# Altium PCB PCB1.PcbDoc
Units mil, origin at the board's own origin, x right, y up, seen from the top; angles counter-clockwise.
Board outline 2484.29 x 2484.29 mil, 2 copper layers (Top Layer, Bottom Layer); 25 components, 9 nets, 53 pads, 3 vias.
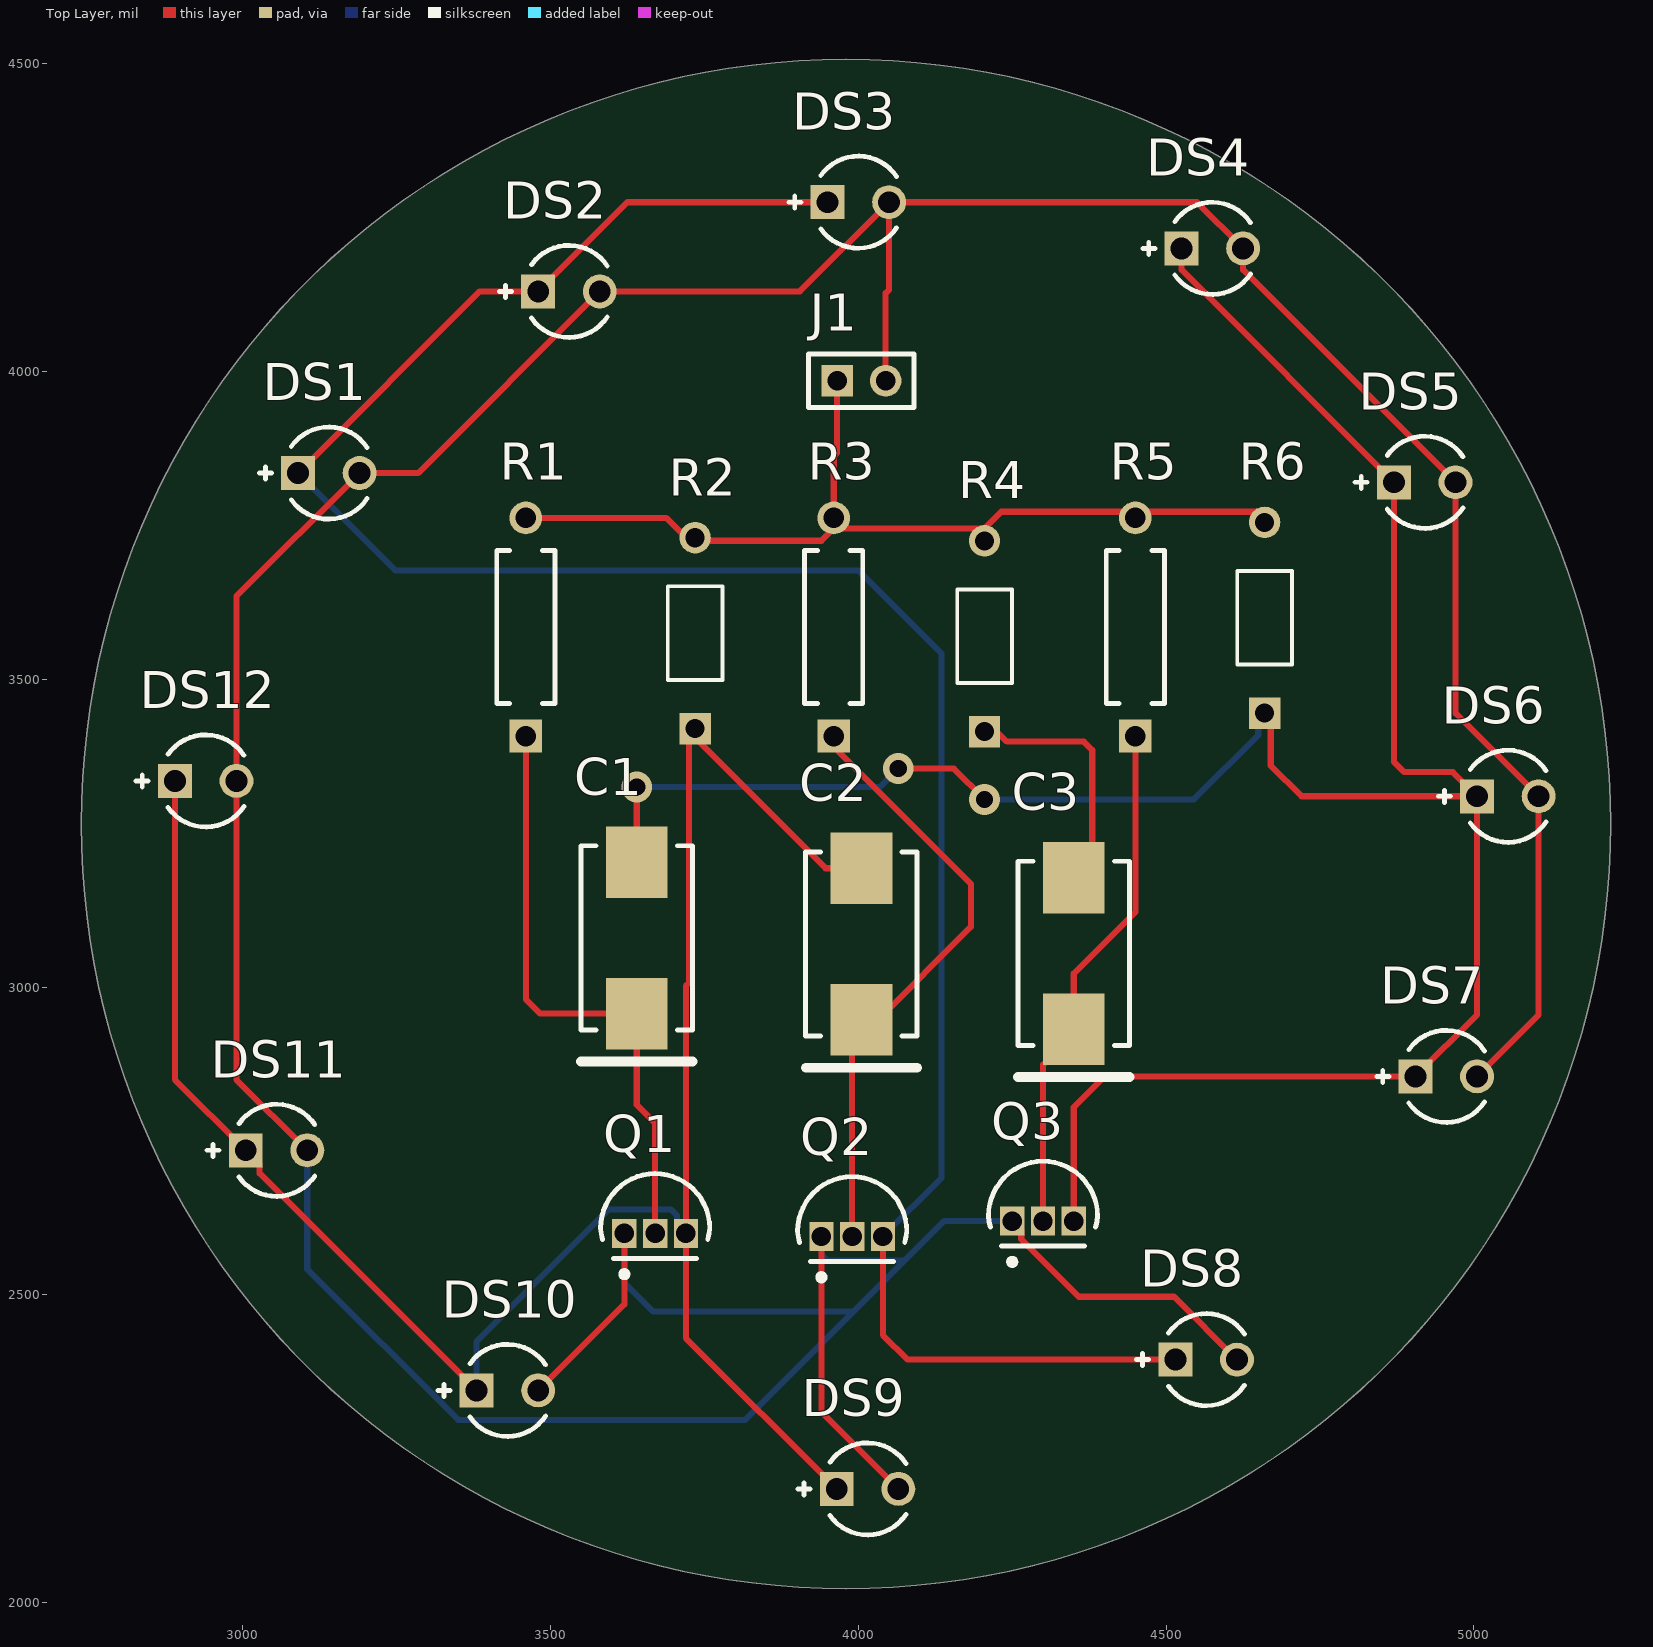
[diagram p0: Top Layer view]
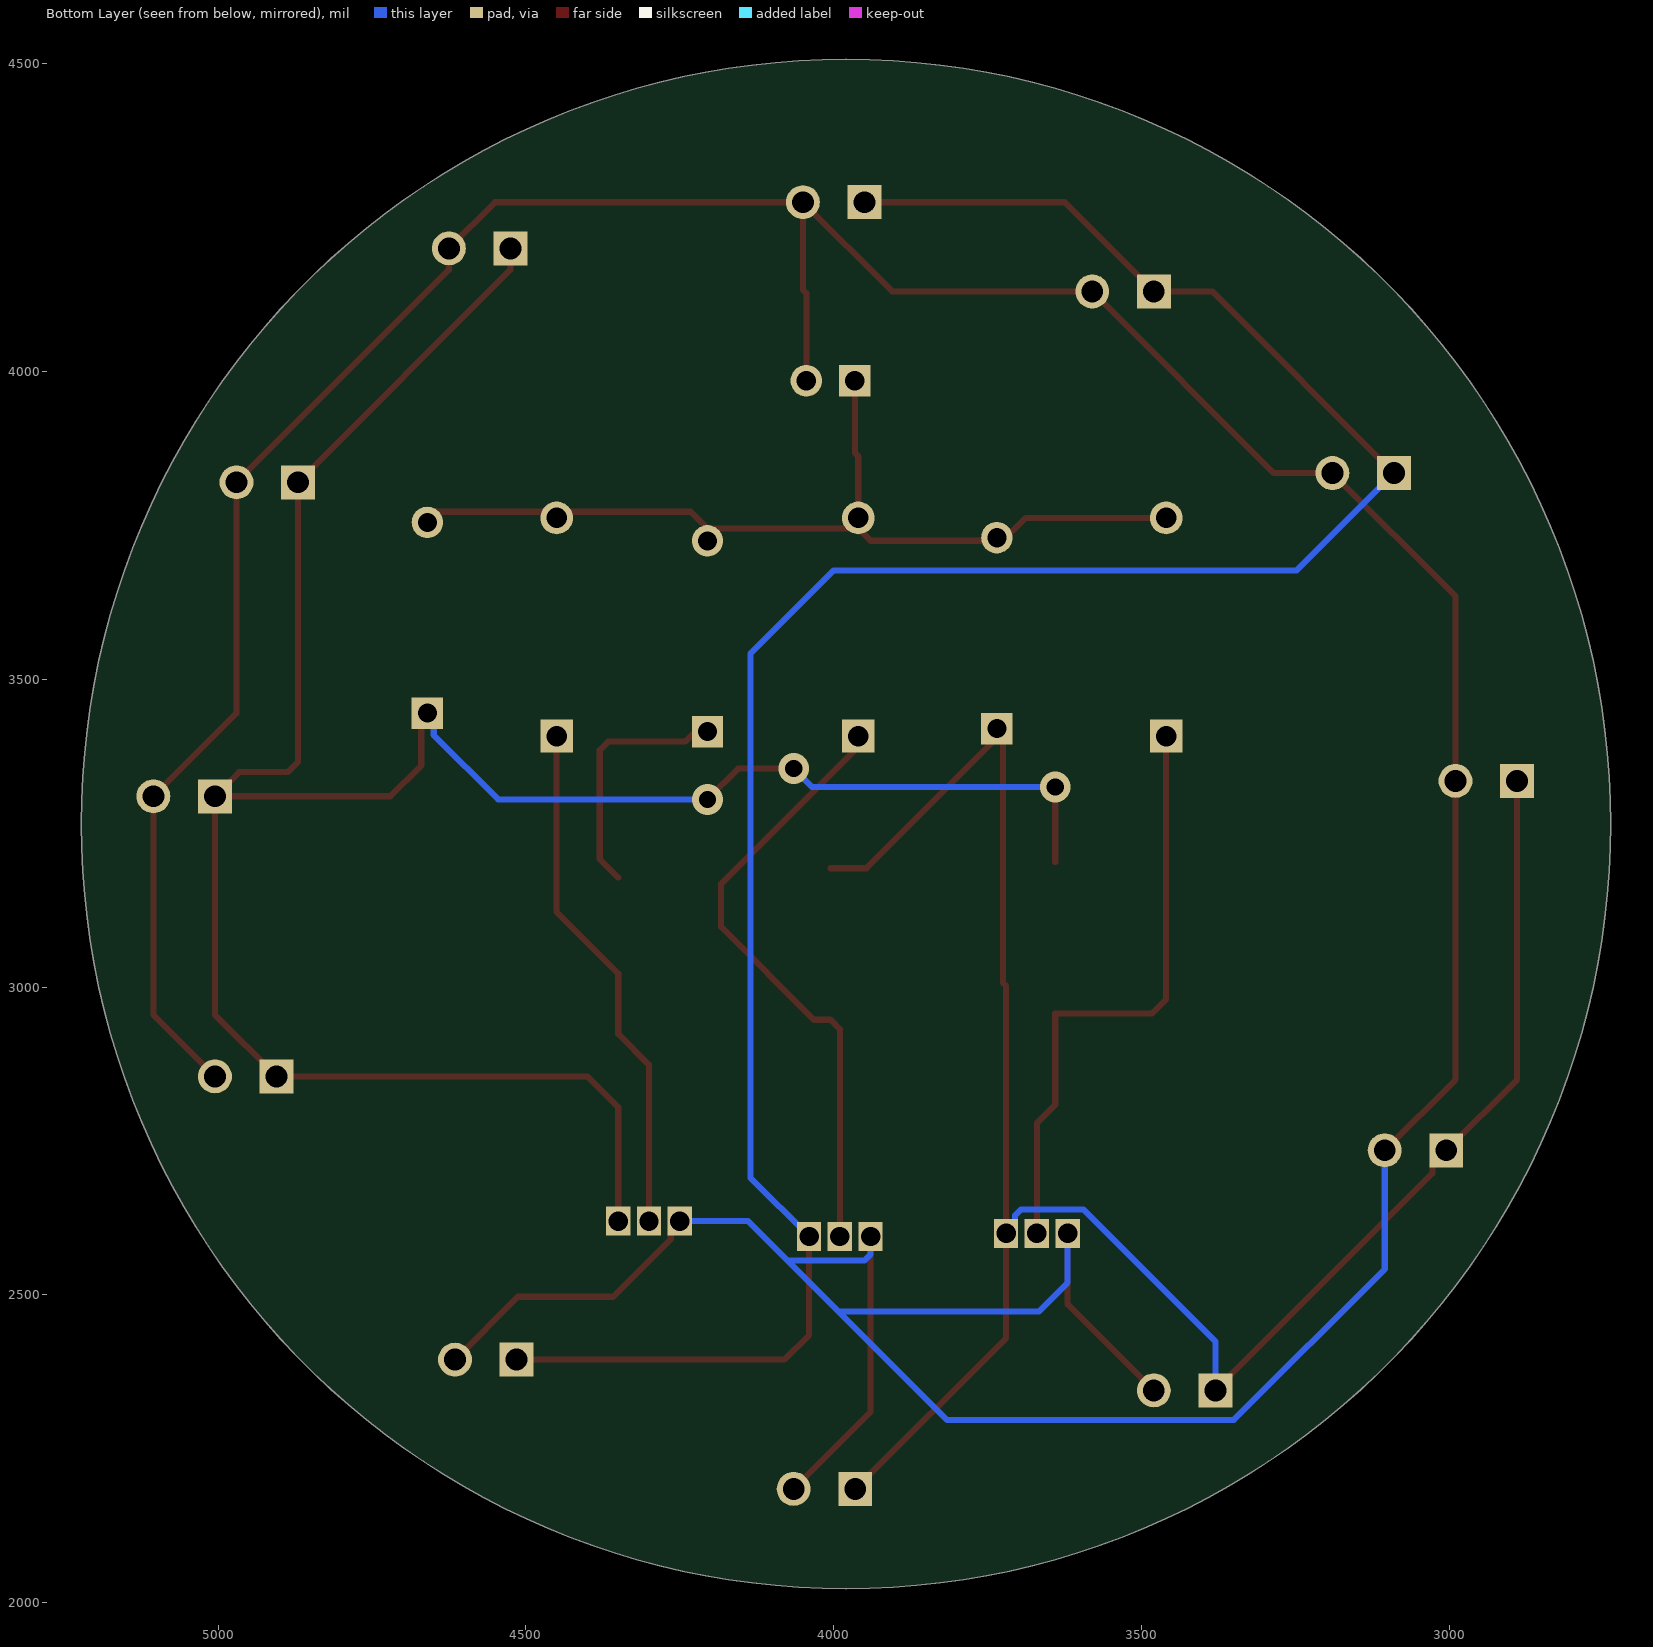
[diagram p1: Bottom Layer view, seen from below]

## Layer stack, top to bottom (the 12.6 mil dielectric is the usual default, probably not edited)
Top Solder: solder mask 0.4, Solder Resist, Dk 3.5
Top Layer: signal copper 1.4
Dielectric 1: dielectric 12.6, FR-4, Dk 4.8
Bottom Layer: signal copper 1.4
Bottom Solder: solder mask 0.4, Solder Resist, Dk 3.5

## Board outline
2737.85,3265 ccw(c3980,3265) 3980,2022.85 ccw(c3980,3265) 5222.15,3265 ccw(c3980,3265) 3980,4507.15 ccw(c3980,3265)

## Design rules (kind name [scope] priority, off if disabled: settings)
Clearance [All] p1: gap=10 ignorepadtopadclearanceinfootprint=FALSE
PolygonConnect [All] p1: connectstyle=Relief reliefconductorwidth=10 reliefentries=4 polygonreliefangle="90 Angle" airgapwidth=10
RoutingVias [All] p1: holewidth=28 width=50 viastyle="Through Hole" minholewidth=28 minwidth=50 maxholewidth=28 maxwidth=50
SolderMaskExpansion [All] p1: expansion=0 istentingtop=FALSE
SupplyNets "Schematic Supply Nets" [InNet('GND')] p1: voltage=0.000
Width [All] p1: maxlimit=10 minlimit=10 preferedwidth=10
30 further rules are at their usual default settings.

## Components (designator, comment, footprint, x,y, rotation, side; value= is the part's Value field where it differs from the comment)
C1 "T491D226K020AT" KEMT-T491-D_M 3640,3080 r90 top value=22µF
C2 "T491D226K020AT" KEMT-T491-D_M 4005,3070 r90 top value=22µF
C3 "T491D226K020AT" KEMT-T491-D_M 4350,3055 r90 top value=22µF
DS1 "LTL-1CHE" INDPR60-254-520X380X650 3140,3835 r0 top
DS2 "LTL-1CHE" INDPR60-254-520X380X650 3530,4130 r0 top
DS3 "LTL-1CHE" INDPR60-254-520X380X650 4000,4275 r0 top
DS4 "LTL-1CHE" INDPR60-254-520X380X650 4575,4200 r0 top
DS5 "LTL-1CHE" INDPR60-254-520X380X650 4920,3820 r0 top
DS6 "LTL-1CHE" INDPR60-254-520X380X650 5055,3310 r0 top
DS7 "LTL-1CHE" INDPR60-254-520X380X650 4955,2855 r0 top
DS8 "LTL-1CHE" INDPR60-254-520X380X650 4565,2395 r0 top
DS9 "LTL-1CHE" INDPR60-254-520X380X650 4015,2185 r0 top
DS10 "LTL-1CHE" INDPR60-254-520X380X650 3430,2345 r0 top
DS11 "LTL-1CHE" INDPR60-254-520X380X650 3055,2735 r0 top
DS12 "LTL-1CHE" INDPR60-254-520X380X650 2940,3335 r0 top
J1 "M22-2510205" FP-M22-2510205-MFG 4005,3985 r0 top
Q1 "S9013" JSCJ-TO-92-3_V 3670,2600 r0 top
Q2 "S9013" JSCJ-TO-92-3_V 3990,2595 r0 top
Q3 "S9013" JSCJ-TO-92-3_V 4300,2620 r0 top
R1 "MFR-25FBF52-10K" RESA60-630X240 3460,3585 r90 top value=10k
R2 "CF18JT330R" STA_CF18_STP 3735,3420 r90 top value=330
R3 "MFR-25FBF52-10K" RESA60-630X240 3960,3585 r90 top value=10k
R4 "CF18JT330R" STA_CF18_STP 4205,3415 r90 top value=330
R5 "MFR-25FBF52-10K" RESA60-630X240 4450,3585 r90 top value=10k
R6 "CF18JT330R" STA_CF18_STP 4660,3445 r90 top value=330

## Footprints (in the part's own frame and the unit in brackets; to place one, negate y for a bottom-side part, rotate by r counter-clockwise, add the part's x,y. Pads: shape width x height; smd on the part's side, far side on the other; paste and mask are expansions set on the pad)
FP-M22-2510205-MFG [mm]
  rect 1.3x1.3 hole 0.8 paste-2539.97 mask+0: 1(-1,0)
  round 1.3 hole 0.8 paste-2539.97 mask+0: 2(1,0)
  silkscreen extent -2.18,-1.1 2.18,1.1, body extent -2.27,-1.2 2.27,1.2, height 0.25
INDPR60-254-520X380X650 [mm] "THD, 2-Leads, Dia 3.8mm, Pitch 2.54mm"
  rect 1.4x1.4 hole 0.9: 1(-1.27,0)
  round 1.4 hole 0.9: 2(1.27,0)
  silkscreen extent -2.87,-1.9 1.58,1.9, body extent -1.9,-1.9 1.9,1.9, height 6.5
JSCJ-TO-92-3_V [mm] "TO-92, 3-leads, Height 4.7mm, Pitch 1.27mm"
  rect 1x1.2 hole 0.8: 1(-1.27,0) 2(0,0) 3(1.27,0)
  silkscreen extent -2.25,-1.81 2.25,2.47, body extent -2.25,-1.03 2.25,2.47, height 4.7
KEMT-T491-D_M [mm] "Molded Capacitor, 2-Leads, Body 7.60x4.60mm, IPC Low Density"
  rect 2.95x2.55 smd: 1(-3.125,0) 2(3.125,0)
  silkscreen extent -5.1,-2.3 3.8,2.3, body extent -3.8,-2.3 3.8,2.3, height 3.1
RESA60-630X240 [mm] "Axial Resistor, 2-Leads, Dia 2.4mm, Body Length 6.3mm"
  rect 1.35x1.35 hole 0.85: 1(-4.5,0)
  round 1.35 hole 0.85: 2(4.5,0)
  silkscreen extent -3.15,-1.2 3.15,1.2, body extent -4.77,-1.19 4.77,1.2, height 2.4
STA_CF18_STP [mil]
  rect 51x51 hole 31 paste-99999 mask+0: 1(0,0)
  round 51 hole 31 paste-99999 mask+0: 2(310,0)
  silkscreen extent 79,-44 231,45, body extent -11,-39 321,39, height 79

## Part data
C1 C2 C3: library part CMP-001-00038-7, "Tantalum Surface Mount Capacitor-Standard Tantalum, 22 uF, +/- 10%, 20 V, -55 to 125 degC, 2917 (7343 Metric), RoHS, Tape and Reel", Capacitor Type=Tantalum, Case/Package=2917, Manufacturer=Kemet, Max Operating Temperature=125°C, Min Operating Temperature=-55°C, Package Description="2-Pin Surface Mount Device, Body 7.3 x 4.3 mm", Package Quantity=500, Package Reference=T491-D, Resistance=0.8Ohm, Ripple Current=433mA, Tolerance=10%, Voltage Rating=20V
DS1 DS2 DS3 DS4 DS5 DS6 DS7 DS8 DS9 DS10 DS11 DS12: library part CMP-007-00018-2, "LED Uni-Color Red, 100 mW, 30 mA, -55 to 100 degC, 2-Pin THD, RoHS, Bulk", Case/Package=Radial, Colour=Red, Forward Current=20mA, Forward Voltage=2V, Manufacturer=Lite-On, Max Operating Temperature=100°C, Min Operating Temperature=-55°C, Package Description="2-Pin Through Hole Device, Dia 3.8 mm, Pitch 2.54 mm", Package Quantity=1000
J1: library part CMP-002-00072-1, "Conn Unshrouded Header M 2 POS 2mm Solder ST Top Entry Thru-Hole Bulk/Loose", Case/Package=SIL, Max Current Rating=1A, Max Operating Temperature=105°C, Min Operating Temperature=-55°C, Voltage Rating=650V
Q1 Q2 Q3: library part CMP-013-00000-3, "Transistor, NPN, 0.1 uA, 150 MHz, 3-Pin TO-92", Case/Package=TO-92-3, Manufacturer="Jiangsu Changjiang Electronics Technology", Package Description="3-Pin Through Hole Device, Height 4.7 mm, Pitch 2.3 mm"
R1 R3 R5: library part CMP-009-00047-4, "Axial Resistor, 10 KOhm, +/- 1%, 0.25 W, -55 to 155 degC, 2-Pin THD, RoHS, Bulk", Case/Package=Axial, Manufacturer=Yageo, Max Operating Temperature=155°C, Min Operating Temperature=-55°C, Package Description="2-Pin Axial Lead, Dia 2.4 mm, Body Length 6.3 mm", Package Quantity=200, Package Reference=MFR-25, Power=250mW, Tolerance=1%, Voltage Rating=250V
R2 R4 R6: library part CMP-009-00177-2, "Fixed Resistor, Carbon Film, 0.125W, 330ohm, 250V, 5% +/-Tol, -400, 0ppm/Cel, Through Hole Mount", Case/Package=Conformal, Max Operating Temperature=155°C, Min Operating Temperature=-55°C, Tolerance=5%

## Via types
v1: diameter 50, hole 28, Top Layer to Bottom Layer, 3 vias

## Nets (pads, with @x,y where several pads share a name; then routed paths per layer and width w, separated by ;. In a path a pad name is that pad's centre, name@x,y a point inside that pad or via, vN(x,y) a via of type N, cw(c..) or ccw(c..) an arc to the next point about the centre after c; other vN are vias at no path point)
GND: DS1.2 DS2.2 DS3.2 DS4.2 DS5.2 DS6.2 DS7.2 DS8.2 DS9.2 DS10.2 DS11.2 DS12.2 J1.2 Q1.1 Q2.1 Q3.1 | length 8210.7
  Top Layer w10: DS11.2 2990,2850 DS12.2 2990,3635 DS1.2 3285,3835 DS2.2 3905,4130 DS3.2 ; DS10.2 3620,2485 Q1.1 ; Q2.1 3940,2310 DS9.2 ; J1.2 4044.37,4127 4050,4132.63 DS3.2 ; Q3.1 4264.69,2605.31 4264.69,2590.79 4358.27,2497.21 4512.79,2497.21 DS8.2 ; DS7.2 5105,2955 DS6.2 4970,3445 DS5.2 4625,4165 DS4.2 4550,4275 DS3.2
  Bottom Layer w10: DS11.2 3105,2542 3350,2297 3816,2297 3992,2473 ; Q1.1 3620,2520 3667,2473 3992,2473 ; Q2.1 3940,2566 3950,2556 4075,2556 ; Q3.1 4139,2620 4075,2556 ; 3992,2473 4075,2556
NetC1_1: C1.1 Q1.2 R1.1 | length 986.8
  Top Layer w10: R1.1 3460,2980 3483.03,2956.97 C1.1 3640,2809 3670,2779 Q1.2
NetC1_2: C1.2 DS4.1 DS5.1 DS6.1 DS7.1 Q3.3 R6.1 | length 4104.9
  Top Layer w10: C1.2 v1(3640,3325) ; v1(4065,3355) 4155,3355 v1(4205,3305) ; Q3.3 4350,2805 4400,2855 DS7.1 5005,2955 DS6.1 ; DS4.1 4525,4165 DS5.1 4870,3365.86 4886.65,3349.21 4965.79,3349.21 DS6.1 ; R6.1@4670,3455 4670,3360 4720,3310 DS6.1
  Bottom Layer w10: v1(3640,3325) 4035,3325 v1(4065,3355) ; v1(4205,3305) 4545,3305 4649.5,3409.5 4649.5,3434.5 R6.1@4670,3455
NetC2_1: C2.1 Q2.2 R3.1 | length 983.8
  Top Layer w10: R3.1@3960,3390.67 4183,3167.67 4183,3097.97 4032,2946.97 C2.1 3990,2931.97 Q2.2
NetC2_2: C2.2 DS9.1 DS10.1 DS11.1 DS12.1 Q1.3 R2.1 | length 3431.2
  Top Layer w10: DS12.1 2890,2850 DS11.1 3027.56,2712.44 3027.56,2697.44 DS10.1 ; DS9.1 3720,2430 Q1.3 3720,3002 3725,3007 3725,3415 3946.97,3193.03 C2.2
  Bottom Layer w10: DS10.1 3380,2424.52 3594.1,2638.62 3695.9,2638.62 3705.31,2629.21 3705.31,2614.69 Q1.3
NetC3_1: C3.1 Q3.2 R5.1 | length 860
  Top Layer w10: Q3.2 4300,2874.09 4350,2924.09 C3.1 4350,3022 4450,3122 R5.1@4450,3417.83
NetC3_2: C3.2 R4.1 | length 415.1
  Top Layer w10: R4.1@4205,3435 4241.25,3398.75 4366.25,3398.75 4380,3385 4380,3208.03 C3.2
NetDS1_1: DS1.1 DS2.1 DS3.1 DS8.1 Q2.3 | length 3846.5
  Top Layer w10: DS1.1 3385,4130 DS2.1 3625,4275 DS3.1 ; Q2.3 4040,2435 4080,2395 DS8.1
  Bottom Layer w10: DS1.1 3248,3677 4000,3677 4135,3542 4135,2690 Q2.3
NetJ1_1: J1.1 R1.2 R2.2 R3.2 R4.2 R5.2 R6.2 | length 1490.2
  Top Layer w10: R1.2 3687.83,3762.17 3725,3725 3940,3725 R3.2@3960,3745 ; J1.1 3965.63,3867.63 3960,3862 R3.2@3960,3745 ; R6.2@4670,3765 4662.83,3772.17 4450,3772.17 4232.17,3772.17 4205,3745 R3.2@3960,3745

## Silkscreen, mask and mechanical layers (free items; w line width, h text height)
Mechanical 1:
  circle w10: c3980,3265 r1242.15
